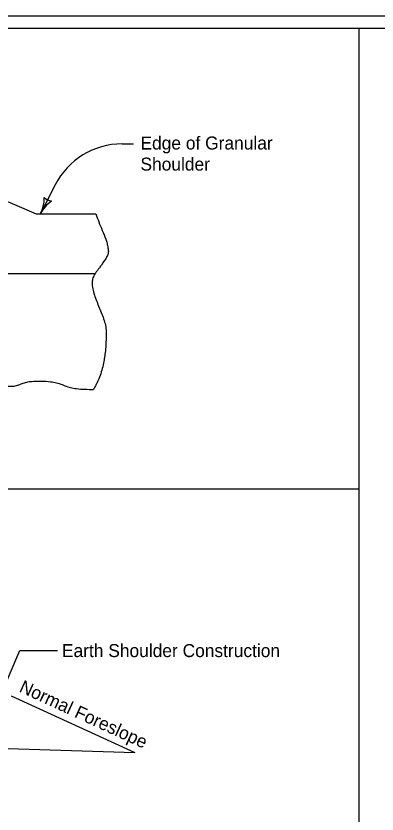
# Model space of a CAD drawing. Extents: x 9538 to 81668, y 7600 to 11751.
# Drawn here: x 15480 to 15925, y 8961 to 9944 of the extents above; entities that cross this region are included whole.
import ezdxf

# ---------------------------------------------------------------- set-up
doc = ezdxf.new("R2010")
doc.units = 0
for name, color, linetype in [('Default', 7, 'Continuous'), ('dsnStdNameDate', 7, 'Continuous'), ('dsnStdNote', 7, 'Continuous'), ('dsnStdShading', 7, 'Continuous'), ('dsnStdTable', 7, 'Continuous')]:
    doc.layers.add(name, color=color, linetype=linetype)

msp = doc.modelspace()

# ---------------------------------------------------------------- linework, layer by layer
at = {"layer": 'Default'}
msp.add_lwpolyline([(13732.53, 9944.02), (16867.53, 9944.02), (16867.53, 7924.02), (13732.53, 7924.02)], close=True, dxfattribs=at)
at = {"layer": 'dsnStdNameDate'}
for p, q in [((15903.11, 8319.02), (15903.11, 9929.02)), ((15903.11, 9361.02), (13747.53, 9361.02))]:
    msp.add_line(p, q, dxfattribs=at)
at = {"layer": 'dsnStdNote'}
for p, q in [((15610.81, 9786.34), (15625.11, 9786.34)), ((15528.5, 9735.97), (15510.27, 9700.29)), ((15450.71, 9082.58), (15484.98, 9162)), ((15484.98, 9162), (15531.35, 9162))]:
    msp.add_line(p, q, dxfattribs=at)
for centre, radius, start, end in [((15610.81, 9693.91), 92.43, 90, 152.9341), ((15472.42, 9719.63), 42.5, 332.9341, 1.00659), ((15526.48, 9732.02), 16.42, 225.20075, 260.66745), ((15548.11, 9680.95), 42.5, 124.86161, 152.9341)]:
    msp.add_arc(centre, radius, start, end, dxfattribs=at)
at = {"layer": 'dsnStdShading'}
msp.add_line((13747.53, 9929.02), (16843.22, 9929.02), dxfattribs=at)
at = {"layer": 'dsnStdTable'}
for p, q in [((15400.84, 9744.89), (15504.88, 9700.29)), ((15526.52, 9732.09), (15510.27, 9700.29)), ((15504.88, 9700.29), (15578.73, 9700.29)), ((14152, 9626.66), (15577.73, 9626.66)), ((15474.01, 9106.17), (15626.55, 9036.24)), ((15143.21, 9052.03), (15626.55, 9036.24))]:
    msp.add_line(p, q, dxfattribs=at)
for points in [[(15578.73, 9700.29), (15582.18, 9690.15), (15586.55, 9679.77), (15590.71, 9669.14), (15592.36, 9663.73), (15593.54, 9658.26), (15593.92, 9652.88), (15593.72, 9651.51), (15593.39, 9650.15), (15592.28, 9647.57), (15585.35, 9637.07), (15583.44, 9634.43), (15581.48, 9631.81), (15579.53, 9629.19), (15577.63, 9626.52), (15575, 9621.14), (15573.99, 9615.65), (15574.19, 9611.8), (15574.76, 9607.94), (15576.77, 9600.17), (15582.83, 9584.51), (15588.83, 9568.79), (15590.75, 9560.94), (15591.4, 9553.1), (15591.18, 9544.51), (15590.7, 9535.86), (15589.82, 9527.13), (15589.2, 9522.79), (15588.47, 9518.46), (15586.5, 9509.66), (15583.76, 9501.06), (15580.18, 9492.41), (15578.02, 9488.11), (15576.84, 9485.97), (15575.6, 9483.83)], [(15295.89, 9487.58), (15297.89, 9487.69), (15305.46, 9488.17), (15313.03, 9488.83), (15320.58, 9489.63), (15328.11, 9490.54), (15332.86, 9491.54), (15337.54, 9492.98), (15342.21, 9494.34), (15344.56, 9494.83), (15346.93, 9495.1), (15353.47, 9495.09), (15360.06, 9494.43), (15366.64, 9493.39), (15373.16, 9492.25), (15377.17, 9491.31), (15381.14, 9490.11), (15385.12, 9488.98), (15389.13, 9488.26), (15392.67, 9488.23), (15396.22, 9488.73), (15403.33, 9490.66), (15410.47, 9492.67), (15417.64, 9493.39), (15432.17, 9492.42), (15446.72, 9491.11), (15453.44, 9490.29), (15460.14, 9489.3), (15466.84, 9488.36), (15473.52, 9487.69), (15479.27, 9488.25), (15484.95, 9490.08), (15490.61, 9492.13), (15496.33, 9493.39), (15503.83, 9493.9), (15511.43, 9494.03), (15522.82, 9493.33), (15526.55, 9492.82), (15533.57, 9491), (15540.47, 9488.43), (15547.39, 9486.06), (15554.49, 9484.83), (15575.6, 9483.83)]]:
    msp.add_spline(points, degree=3, dxfattribs=at)

# ---------------------------------------------------------------- texts
at = {"layer": 'dsnStdNote'}
for s, p in [('Edge of Granular ', (15633.55, 9779.46)), ('Shoulder', (15633.55, 9753.46)), ('Earth Shoulder Construction', (15536.81, 9154))]:
    msp.add_text(s, height=16, dxfattribs=at).set_placement(p)
msp.add_text('Normal Foreslope', height=16, rotation=335.37202, dxfattribs=at).set_placement((15482.93, 9111.78))

doc.saveas('drawing.dxf')
